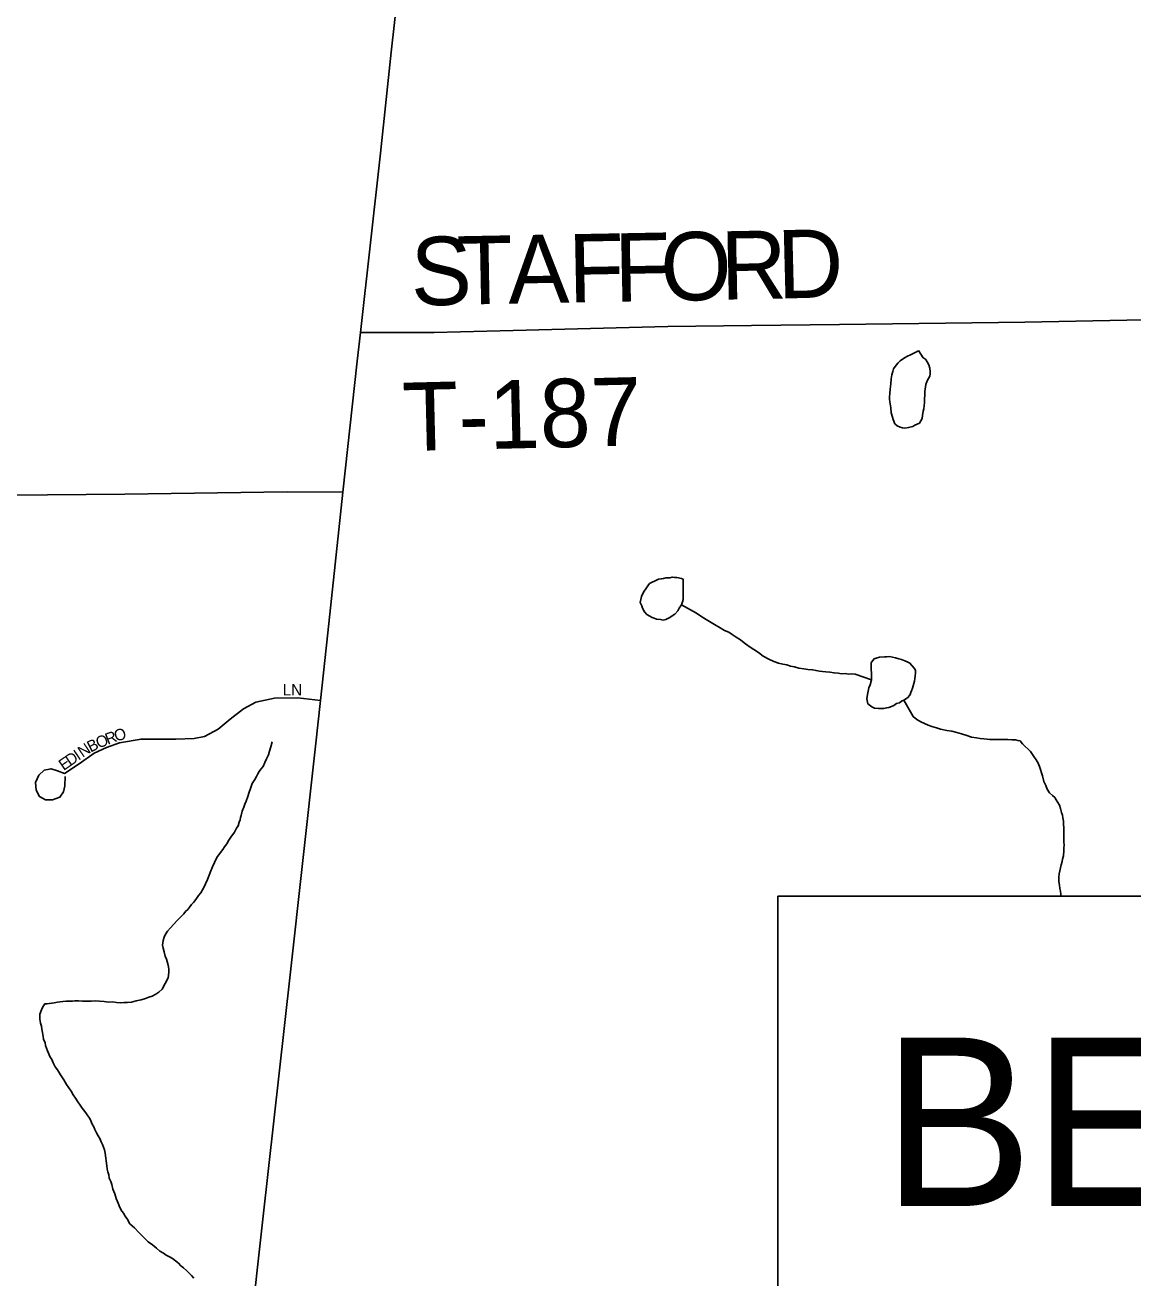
# Model space of a CAD drawing. Extents: x 10.6 to 44.6, y -2.6 to 23.4.
# Drawn here: x 13.881 to 14.801, y 19.247 to 20.288 of the extents above; entities that cross this region are included whole.
import ezdxf

# ---------------------------------------------------------------- set-up
doc = ezdxf.new("R2010")
doc.units = 0
for name, color, linetype in [('GM_X_Minor_Lake', 7, 'Continuous'), ('GM_X_Minor_River', 7, 'Continuous'), ('GM_X_State_Route', 7, 'Continuous'), ('GM_X_Township_Road', 7, 'Continuous'), ('GM_X_Township_Road_Text', 7, 'Continuous'), ('GM_X_Township_Subdivision', 7, 'Continuous'), ('GM_X_Township_Subdivision_Text', 7, 'Continuous'), ('SH_Border', 7, 'Continuous'), ('SH_Text', 7, 'Continuous')]:
    doc.layers.add(name, color=color, linetype=linetype)

msp = doc.modelspace()

# ---------------------------------------------------------------- linework, layer by layer
at = {"layer": 'GM_X_Minor_Lake'}
for points in [[(14.6227, 20.0179), (14.6223, 20.0175), (14.619, 20.0156), (14.6163, 20.0144), (14.6137, 20.0132), (14.6118, 20.012), (14.6095, 20.0108), (14.6077, 20.0092), (14.6058, 20.0077), (14.6043, 20.0058), (14.6021, 20.0027), (14.6014, 20.0004), (14.6007, 19.9977), (14.6, 19.9943), (14.5997, 19.9901), (14.5994, 19.9859), (14.5991, 19.9821), (14.5988, 19.9794), (14.5988, 19.9775), (14.5989, 19.9752), (14.5998, 19.9703), (14.6002, 19.9661), (14.6011, 19.9624), (14.6019, 19.9605), (14.6031, 19.9571), (14.605, 19.9552), (14.6077, 19.9541), (14.6096, 19.9538)], [(14.6227, 20.0179), (14.6223, 20.0175), (14.619, 20.0156), (14.6163, 20.0144), (14.6137, 20.0132), (14.6118, 20.012), (14.6095, 20.0108), (14.6077, 20.0092), (14.6058, 20.0077), (14.6043, 20.0058), (14.6021, 20.0027), (14.6014, 20.0004), (14.6007, 19.9977), (14.6, 19.9943), (14.5997, 19.9901), (14.5994, 19.9859), (14.5991, 19.9821), (14.5988, 19.9794), (14.5988, 19.9775), (14.5989, 19.9752), (14.5998, 19.9703), (14.6002, 19.9661), (14.6011, 19.9624), (14.6019, 19.9605), (14.6031, 19.9571), (14.605, 19.9552), (14.6077, 19.9541), (14.6096, 19.9538), (14.6115, 19.9535), (14.6146, 19.9539), (14.618, 19.9547), (14.6198, 19.9559), (14.6217, 19.9567), (14.6236, 19.9575), (14.6258, 19.9614), (14.6261, 19.964), (14.6268, 19.9675), (14.6272, 19.9694), (14.6275, 19.9721), (14.6278, 19.9743), (14.6278, 19.977), (14.6281, 19.9816), (14.628, 19.9838), (14.629, 19.9896), (14.6301, 19.9926), (14.6312, 19.9946), (14.6323, 19.9965), (14.6326, 19.9984), (14.6326, 20.0003), (14.6322, 20.0033), (14.6313, 20.006), (14.6301, 20.0086), (14.6286, 20.0108), (14.6266, 20.0119), (14.6227, 20.0179)], [(14.6096, 19.9538), (14.6115, 19.9535), (14.6146, 19.9539), (14.618, 19.9547), (14.6198, 19.9559), (14.6217, 19.9567), (14.6236, 19.9575), (14.6258, 19.9614), (14.6261, 19.964), (14.6268, 19.9675), (14.6272, 19.9694), (14.6275, 19.9721), (14.6278, 19.9743), (14.6278, 19.977), (14.6281, 19.9816), (14.628, 19.9838), (14.629, 19.9896), (14.6301, 19.9926), (14.6312, 19.9946), (14.6323, 19.9965), (14.6326, 19.9984), (14.6326, 20.0003), (14.6322, 20.0033), (14.6313, 20.006), (14.6301, 20.0086), (14.6286, 20.0108), (14.6266, 20.0119), (14.6227, 20.0179)], [(14.4274, 19.8279), (14.4259, 19.8286), (14.4221, 19.8293), (14.4202, 19.8292), (14.4183, 19.8296), (14.4164, 19.8291), (14.413, 19.8291), (14.4111, 19.8286), (14.4092, 19.8282), (14.4069, 19.8278), (14.4035, 19.8262), (14.4016, 19.8254), (14.3994, 19.8242), (14.3979, 19.8223), (14.3964, 19.82), (14.3949, 19.818), (14.3938, 19.8161), (14.3927, 19.8134), (14.3917, 19.8085)], [(14.4274, 19.8279), (14.4259, 19.8286), (14.4221, 19.8293), (14.4202, 19.8292), (14.4183, 19.8296), (14.4164, 19.8291), (14.413, 19.8291), (14.4111, 19.8286), (14.4092, 19.8282), (14.4069, 19.8278), (14.4035, 19.8262), (14.4016, 19.8254), (14.3994, 19.8242), (14.3979, 19.8223), (14.3964, 19.82), (14.3949, 19.818), (14.3938, 19.8161), (14.3927, 19.8134), (14.3917, 19.8085), (14.3929, 19.8058), (14.3937, 19.8039), (14.3953, 19.8009), (14.3972, 19.7987), (14.4015, 19.7961), (14.4034, 19.7954), (14.4053, 19.7947), (14.4084, 19.7944), (14.4107, 19.794), (14.4129, 19.7945), (14.4156, 19.7957), (14.4204, 19.7988), (14.423, 19.8015), (14.4241, 19.8038), (14.426, 19.8065), (14.4267, 19.8092), (14.4274, 19.8111), (14.4274, 19.8279)], [(14.3917, 19.8085), (14.3929, 19.8058), (14.3937, 19.8039), (14.3953, 19.8009), (14.3972, 19.7987), (14.4015, 19.7961), (14.4034, 19.7954), (14.4053, 19.7947), (14.4084, 19.7944), (14.4107, 19.794), (14.4129, 19.7945), (14.4156, 19.7957), (14.4204, 19.7988), (14.423, 19.8015), (14.4241, 19.8038), (14.426, 19.8065), (14.4267, 19.8092), (14.4274, 19.8111), (14.4274, 19.8279)], [(14.5834, 19.7583), (14.5837, 19.7442), (14.5826, 19.74), (14.5815, 19.7377), (14.5805, 19.732), (14.5798, 19.7286), (14.5807, 19.7244), (14.5841, 19.7218), (14.5864, 19.7207), (14.5895, 19.7204), (14.5914, 19.7204), (14.5941, 19.7205), (14.5963, 19.7209), (14.5982, 19.7214), (14.6005, 19.7222), (14.6024, 19.723), (14.6046, 19.7245), (14.6069, 19.7253), (14.6088, 19.7265), (14.6106, 19.7273), (14.6136, 19.7293), (14.6155, 19.7316), (14.6169, 19.7351), (14.6177, 19.7374), (14.6184, 19.7393), (14.6194, 19.7431), (14.6198, 19.7454), (14.6201, 19.7473), (14.6204, 19.75), (14.6204, 19.7522), (14.6192, 19.7541), (14.6157, 19.7582), (14.6134, 19.7593), (14.6115, 19.76), (14.6088, 19.7611), (14.6065, 19.7618), (14.6038, 19.7625), (14.6011, 19.7632), (14.5988, 19.7636), (14.5966, 19.7635), (14.5947, 19.7635), (14.5905, 19.763), (14.5886, 19.7626), (14.5859, 19.7618), (14.5837, 19.759), (14.5834, 19.7583)], [(14.5834, 19.7583), (14.5837, 19.7442), (14.5826, 19.74), (14.5815, 19.7377), (14.5805, 19.732), (14.5798, 19.7286), (14.5807, 19.7244), (14.5841, 19.7218), (14.5864, 19.7207), (14.5895, 19.7204), (14.5914, 19.7204), (14.5941, 19.7205), (14.5963, 19.7209), (14.5982, 19.7214), (14.6005, 19.7222), (14.6024, 19.723), (14.6046, 19.7245), (14.6069, 19.7253), (14.6088, 19.7265), (14.6106, 19.7273), (14.6136, 19.7293), (14.6155, 19.7316), (14.6169, 19.7351)], [(14.6169, 19.7351), (14.6177, 19.7374), (14.6184, 19.7393), (14.6194, 19.7431), (14.6198, 19.7454), (14.6201, 19.7473), (14.6204, 19.75), (14.6204, 19.7522), (14.6192, 19.7541), (14.6157, 19.7582), (14.6134, 19.7593), (14.6115, 19.76), (14.6088, 19.7611), (14.6065, 19.7618), (14.6038, 19.7625), (14.6011, 19.7632), (14.5988, 19.7636), (14.5966, 19.7635), (14.5947, 19.7635), (14.5905, 19.763), (14.5886, 19.7626), (14.5859, 19.7618), (14.5837, 19.759), (14.5834, 19.7583)]]:
    msp.add_lwpolyline(points, dxfattribs=at)
at = {"layer": 'GM_X_Minor_River'}
for points in [[(14.426, 19.8065), (14.4383, 19.7996), (14.4429, 19.7966), (14.4479, 19.7937), (14.4533, 19.7904), (14.458, 19.7875), (14.4618, 19.7853), (14.4653, 19.7838), (14.468, 19.782), (14.4714, 19.7798), (14.4749, 19.7776), (14.478, 19.775), (14.4823, 19.772), (14.4861, 19.7695), (14.49, 19.7669), (14.4938, 19.7639), (14.4985, 19.7614), (14.5027, 19.7596), (14.5065, 19.7581), (14.51, 19.7574), (14.5134, 19.7568), (14.5165, 19.7557), (14.5199, 19.755), (14.5233, 19.7539), (14.5275, 19.7533), (14.531, 19.753), (14.5348, 19.7527), (14.5378, 19.752), (14.5405, 19.7516), (14.5432, 19.7513), (14.5459, 19.751), (14.5493, 19.7507), (14.5527, 19.75), (14.5562, 19.7497), (14.5588, 19.7494), (14.5622, 19.7495), (14.5645, 19.7491), (14.5672, 19.7492), (14.5702, 19.7489), (14.5837, 19.7442)], [(14.6106, 19.7273), (14.6185, 19.7138), (14.6213, 19.7112), (14.6247, 19.7094), (14.6278, 19.7079), (14.6309, 19.7065), (14.6339, 19.7054), (14.6378, 19.7044), (14.6412, 19.7033), (14.6462, 19.7023), (14.6504, 19.7016), (14.6546, 19.7005), (14.6584, 19.6995), (14.663, 19.6981), (14.6668, 19.6966), (14.671, 19.696), (14.6741, 19.6956), (14.6771, 19.6953), (14.6798, 19.695), (14.6821, 19.6947), (14.6855, 19.6948), (14.6882, 19.6948), (14.6969, 19.6946), (14.7004, 19.6943), (14.7034, 19.6944), (14.7053, 19.694), (14.7072, 19.6937), (14.7092, 19.6911), (14.7115, 19.6889), (14.7138, 19.6866), (14.7158, 19.6848), (14.7185, 19.6807), (14.7205, 19.6777), (14.7221, 19.675), (14.7233, 19.6724), (14.7241, 19.6698), (14.7249, 19.6671), (14.7257, 19.6645), (14.727, 19.6599), (14.7286, 19.6565), (14.7298, 19.6535), (14.7317, 19.6505), (14.7341, 19.6483), (14.736, 19.6464), (14.7372, 19.6446), (14.7384, 19.6423), (14.7399, 19.6401), (14.7408, 19.6374), (14.7416, 19.634), (14.7424, 19.6318), (14.7428, 19.6295), (14.7433, 19.6268), (14.7433, 19.6246), (14.7434, 19.6211), (14.7435, 19.6177), (14.7435, 19.6147), (14.7436, 19.612), (14.7436, 19.6094), (14.7437, 19.6071), (14.7434, 19.6044), (14.7434, 19.6021), (14.7431, 19.598), (14.7424, 19.5953), (14.7421, 19.5934), (14.7414, 19.5907), (14.7396, 19.5831), (14.7393, 19.5804), (14.7394, 19.5766), (14.7398, 19.5736), (14.7403, 19.5709), (14.7407, 19.5686), (14.7411, 19.566), (14.7414, 19.5646)], [(14.086, 19.6927), (14.085, 19.6885), (14.0839, 19.6851), (14.0829, 19.682), (14.0814, 19.6786), (14.08, 19.6755), (14.0785, 19.6724), (14.0766, 19.6701), (14.0752, 19.6682), (14.0741, 19.6663), (14.073, 19.6639), (14.0715, 19.6616), (14.0693, 19.6582), (14.0679, 19.654), (14.0668, 19.6509), (14.0657, 19.6474), (14.0643, 19.6436), (14.0632, 19.6409), (14.0625, 19.6386), (14.061, 19.6352), (14.0603, 19.6317), (14.0596, 19.6298), (14.0593, 19.6279), (14.0586, 19.626), (14.0579, 19.623), (14.0564, 19.621), (14.0546, 19.6176), (14.0516, 19.6137), (14.0501, 19.611), (14.0483, 19.6079), (14.0464, 19.6056), (14.045, 19.6033), (14.0405, 19.5975), (14.0394, 19.5956), (14.038, 19.5925), (14.0365, 19.589), (14.0351, 19.5856), (14.0336, 19.5821), (14.0322, 19.5783), (14.0307, 19.5749), (14.0293, 19.5718), (14.0282, 19.5699), (14.0267, 19.5672), (14.0249, 19.5652), (14.0226, 19.5618), (14.0208, 19.5594), (14.0189, 19.5575), (14.0175, 19.5556), (14.016, 19.5536), (14.0141, 19.5517), (14.0126, 19.5498), (14.0089, 19.5459), (14.007, 19.5443), (14.0044, 19.5412), (14.0015, 19.5381), (13.9992, 19.5354), (13.997, 19.5323), (13.9963, 19.5304), (13.9956, 19.5277), (13.9953, 19.5258), (13.9949, 19.5239), (13.9954, 19.5213), (13.9962, 19.5182), (13.997, 19.5148), (13.9982, 19.5122), (13.9994, 19.5084), (13.9999, 19.5058), (14.0003, 19.5035), (14.0003, 19.5016), (14, 19.4986), (13.9997, 19.4967), (13.9946, 19.4874), (13.992, 19.4847), (13.9893, 19.4831), (13.9863, 19.4815), (13.9837, 19.4807), (13.9807, 19.4795), (13.9773, 19.4783), (13.9731, 19.4775), (13.9693, 19.4766), (13.9659, 19.4762), (13.9628, 19.4761), (13.9602, 19.476), (13.9568, 19.4763), (13.9537, 19.4767), (13.9499, 19.4766), (13.9465, 19.4769), (13.9427, 19.4772), (13.9389, 19.4775), (13.9358, 19.4774), (13.9324, 19.4773), (13.9286, 19.4773), (13.9252, 19.4776), (13.9221, 19.4775), (13.9202, 19.4774), (13.9183, 19.4774), (13.9149, 19.4773), (13.9122, 19.4769), (13.91, 19.4768), (13.9077, 19.4764), (13.905, 19.476)], [(13.905, 19.476), (13.9031, 19.4756), (13.9009, 19.4755), (13.899, 19.4751), (13.8971, 19.475), (13.8956, 19.4727), (13.8945, 19.47), (13.8931, 19.4666), (13.8931, 19.4624), (13.8936, 19.459), (13.8944, 19.4564), (13.8948, 19.4541), (13.8953, 19.4514), (13.8957, 19.448), (13.8962, 19.4458), (13.8974, 19.4427), (13.8978, 19.4405), (13.8986, 19.4382), (13.8994, 19.436), (13.9002, 19.4341), (13.9014, 19.4314), (13.903, 19.4288), (13.9042, 19.4262), (13.9058, 19.4228), (13.9077, 19.4202), (13.9101, 19.416), (13.9129, 19.4119), (13.9152, 19.4082), (13.9172, 19.4052), (13.9191, 19.4026), (13.9207, 19.3996), (13.9227, 19.3966), (13.9247, 19.3936), (13.9266, 19.3909), (13.9282, 19.3883), (13.9305, 19.3857), (13.9317, 19.3838), (13.9329, 19.382), (13.9345, 19.3797), (13.9353, 19.3778), (13.9365, 19.3752), (13.938, 19.3729), (13.9388, 19.3707), (13.94, 19.368), (13.9416, 19.3654), (13.9428, 19.3632), (13.944, 19.3605), (13.9452, 19.3583), (13.946, 19.356), (13.9468, 19.3538), (13.9473, 19.3511), (13.9486, 19.3405), (13.9491, 19.3378), (13.9495, 19.3356), (13.9503, 19.3329), (13.9507, 19.3303), (13.9519, 19.3276), (13.9528, 19.325), (13.9536, 19.3212), (13.9552, 19.3171), (13.9564, 19.3133), (13.958, 19.3095), (13.9596, 19.3058), (13.9612, 19.3028), (13.9628, 19.3009), (13.9636, 19.299), (13.9655, 19.2964), (13.9679, 19.2923), (13.9718, 19.2889), (13.9753, 19.2852), (13.9792, 19.2811), (13.9831, 19.2774), (13.9865, 19.2748), (13.99, 19.2722), (13.9927, 19.2696), (13.9958, 19.2678), (13.9981, 19.2663), (14.0008, 19.2649), (14.0031, 19.2634), (14.0058, 19.2615), (14.0082, 19.2597), (14.0101, 19.2575), (14.0124, 19.2556), (14.0148, 19.2534), (14.0167, 19.2515), (14.019, 19.2493), (14.021, 19.2471)]]:
    msp.add_lwpolyline(points, dxfattribs=at)
at = {"layer": 'GM_X_State_Route'}
msp.add_lwpolyline([(14.0568, 19.1037), (14.0782, 19.2961), (14.1009, 19.4992), (14.122, 19.6891), (14.1261, 19.7272), (14.1323, 19.7834), (14.1413, 19.8688), (14.1446, 19.9003), (14.1565, 20.009), (14.1594, 20.0328), (14.1759, 20.1819), (14.1848, 20.2658), (14.1959, 20.3647)], dxfattribs=at)
at = {"layer": 'GM_X_Township_Road'}
for points in [[(14.1594, 20.0328), (14.2205, 20.033), (14.2862, 20.0345), (14.4146, 20.0379), (14.4842, 20.0387), (14.5573, 20.0394), (14.7111, 20.0414), (14.8241, 20.0436), (14.9602, 20.0456), (15.0422, 20.0468), (15.0851, 20.047), (15.1285, 20.0483), (15.1717, 20.0486), (15.2064, 20.0496), (15.2452, 20.0496), (15.2699, 20.0496)], [(13.2033, 19.8741), (13.2729, 19.8794), (13.3655, 19.8863), (13.4427, 19.8912), (13.4814, 19.8937), (13.5151, 19.8938), (13.548, 19.8943), (13.6006, 19.8953), (13.7182, 19.8962), (13.7384, 19.8967), (13.7972, 19.8972), (13.8674, 19.8976), (13.9635, 19.8986), (14.0985, 19.9005), (14.1446, 19.9003)]]:
    msp.add_lwpolyline(points, dxfattribs=at)
at = {"layer": 'GM_X_Township_Subdivision'}
msp.add_lwpolyline([(13.914, 19.6639), (13.9138, 19.6563), (13.9128, 19.6513), (13.9097, 19.6468), (13.9036, 19.6447), (13.8978, 19.6447), (13.8928, 19.6473), (13.89, 19.6527), (13.8895, 19.6589), (13.8921, 19.6651), (13.8967, 19.6692), (13.9024, 19.6704), (13.9078, 19.6687), (13.9136, 19.6666), (13.9257, 19.6746), (13.9383, 19.6834), (13.9483, 19.688), (13.9592, 19.692), (13.9771, 19.6951), (14.0061, 19.6951), (14.0211, 19.6956), (14.0299, 19.6973), (14.0411, 19.7032), (14.0511, 19.7115), (14.0621, 19.7201), (14.0725, 19.7258), (14.088, 19.7291), (14.1073, 19.7294), (14.1261, 19.7272)], dxfattribs=at)
at = {"layer": 'SH_Border'}
msp.add_lwpolyline([(14.506, 19.5646), (16.2314, 19.5646), (16.2314, 18.9996), (14.506, 18.9996)], close=True, dxfattribs=at)

# ---------------------------------------------------------------- texts
at = {"layer": 'GM_X_Township_Road_Text'}
for s, height, rotation, p in [('S', 0.0568, 1.0787, (14.2016, 20.0552)), ('T', 0.0568, 1.0757, (14.2399, 20.056)), ('A', 0.0568, 1.0796, (14.2824, 20.0568)), ('F', 0.0568, 1.0786, (14.3324, 20.0577)), ('F', 0.0568, 1.0786, (14.3707, 20.0584)), ('O', 0.0568, 1.0783, (14.409, 20.0591)), ('R', 0.0568, 1.08, (14.459, 20.0601)), ('D', 0.0568, 1.4198, (14.5061, 20.061)), ('T-187', 0.05682, 1.3983, (14.1949, 19.9343))]:
    msp.add_text(s, height=height, rotation=rotation, dxfattribs=at).set_placement(p)
at = {"layer": 'GM_X_Township_Subdivision_Text'}
for s, rotation, p in [('LN', 0, (14.0947, 19.7313)), ('B', 26.4782, (13.9352, 19.6838)), ('O', 21.9475, (13.9418, 19.6871)), ('R', 21.2241, (13.9495, 19.6902)), ('O', 16.5339, (13.9563, 19.6929)), ('I', 34.4689, (13.9252, 19.677)), ('N', 33.9568, (13.9286, 19.6794)), ('E', 34.4705, (13.9128, 19.6685)), ('D', 34.4736, (13.9183, 19.6723))]:
    msp.add_text(s, height=0.00947, rotation=rotation, dxfattribs=at).set_placement(p)
at = {"layer": 'SH_Text'}
msp.add_text('BEGIN PROJECT', height=0.14, dxfattribs=at).set_placement((14.5929, 19.3071))

doc.saveas('drawing.dxf')
